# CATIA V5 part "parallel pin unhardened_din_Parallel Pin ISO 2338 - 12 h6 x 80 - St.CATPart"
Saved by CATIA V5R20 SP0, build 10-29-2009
Part number: parallel pin unhardened_din_Parallel Pin ISO 2338 - 12 h6 x 80 - St
Revision: ANY
Definition: UNKNOWN
Nomenclature: parallel pin unhardened_din_Parallel Pin ISO 2338 - 12 h6 x 80 - St
Source: Unknown
Bounding box of the stored display mesh (mm): x 0 to 80, y -5.85 to 5.85, z -6 to 6
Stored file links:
  C:\Users\Utente\Desktop\IO LAVORO\3D X SITO CF\CUMSA\3D files SD\SD 3824\parallel pin unhardened_din_Parallel Pin ISO 2338 - 12 h6 x 80 - St.CATPart
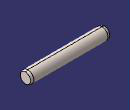
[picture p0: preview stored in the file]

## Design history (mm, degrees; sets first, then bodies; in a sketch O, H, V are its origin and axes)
Body1 "Base-Revolve" (main body)
  Solid1: solid without history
